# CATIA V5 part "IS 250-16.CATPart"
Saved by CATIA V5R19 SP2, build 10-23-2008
Part number: IS 250-16
Bounding box of the stored display mesh (mm): x -18.951 to 18.951, y -18.952 to 18.952, z 0 to 82
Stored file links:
  C:\Users\Bora\Desktop\3D Katı model\IS serisi\IS 250\IS 250-16.CATPart
  C:\Program Files\Dassault Systemes\B19\intel_a\reffiles\standard\MetricThickPitch.txt
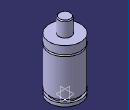
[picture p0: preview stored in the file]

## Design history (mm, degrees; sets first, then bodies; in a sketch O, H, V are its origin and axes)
Body1 (main body)
  Sketch1 on yz-plane, origin (0, 0, 0), H (0, 1, 0), V (0, 0, 1)
    point P3 (7.5, 81)
    point P5 (7.5, 81)
    point P7 (19, 54.5)
    point P8 (19, 52.5)
    point P12 (19, 52.5)
    point P13 (19, 54.5)
    line L1 (19, 0) -> (19, 4)
    line L2 (7.5, 81) -> (7.5, 64)
    arc A1 centre (6.5, 81) radius 1 from (7.5, 81) to (6.5, 82) ccw
    arc A2 centre (19, 53.5) radius 1 from (19, 54.5) to (19, 52.5) ccw
    line L3 (16.5, 7.5) -> (16.5, 4)
    line L4 (19, 7.5) -> (19, 52.5)
    line L5 (19, 54.5) -> (19, 64)
    line L6 (6.5, 82) -> (0, 82)
    point P15 (0, 82)
    line L7 (7.5, 64) -> (19, 64)
    line L8 (0, 0) -> (19, 0)
    line L9 (16.5, 4) -> (19, 4)
    line L10 (16.5, 7.5) -> (19, 7.5)
    tangency: L6 A1
    coincidence: P15 V, P3 P5, P7 P13, P8 P12
    horizontal: L7 H, L8 H, L9 H, L10 H
  Shaft1: profile Sketch1, axis Sketch1.V, angle 360
  Sketch2 on face of Shaft1 from Sketch1.L8, origin (0, 0, 0), H (1, 0, 0), V (0, -1, 0)
    point P1 (0, 0)
  Hole1: placed by Sketch2, at (0, 0, 0) direction (0, 0, 1), diameter 6.647, depth 7, threaded "M8", thread diameter 8, thread depth 7, pitch 1.25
